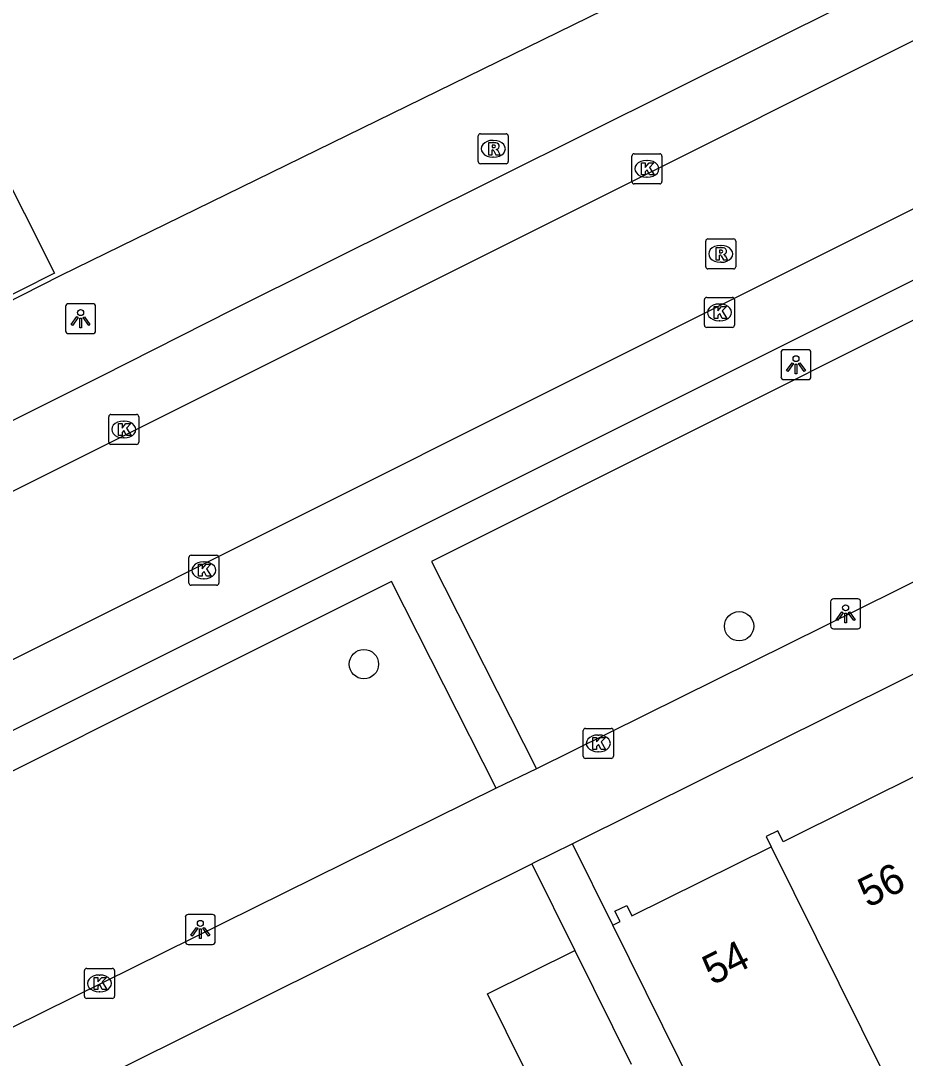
# Model space of a CAD drawing. Extents: x 157793 to 159380, y 380882 to 382313.
# Drawn here: x 158332.75 to 158362.2, y 381485.24 to 381519.79 of the extents above; entities that cross this region are included whole.
import ezdxf

# ---------------------------------------------------------------- set-up
doc = ezdxf.new("R2010")
doc.units = 0
for name, color, linetype in [('IMGEO_Boom', 7, 'Continuous'), ('IMGEO_Kolk', 7, 'Continuous'), ('IMGEO_Lichtpunt', 7, 'Continuous'), ('IMGEO_Pand', 7, 'Continuous'), ('IMGEO_Pand_nummerreeks', 7, 'Continuous'), ('IMGEO_Rijbaan_lokaal_open', 7, 'Continuous'), ('IMGEO_Rioolput', 7, 'Continuous'), ('IMGEO_Voetpad_open', 7, 'Continuous')]:
    doc.layers.add(name, color=color, linetype=linetype)

msp = doc.modelspace()

# ---------------------------------------------------------------- linework, layer by layer
at = {"layer": 'IMGEO_Boom'}
for centre in [(158356.671, 381499.625), (158344.178, 381498.362)]:
    msp.add_circle(centre, 0.489, dxfattribs=at)
at = {"layer": 'IMGEO_Kolk'}
for p, q in [((158353.175, 381515.358), (158354.027, 381515.358)), ((158353.1, 381514.432), (158353.1, 381515.284)), ((158353.588, 381515.138), (158353.613, 381515.138)), ((158354.101, 381515.284), (158354.101, 381514.432)), ((158354.027, 381514.358), (158353.175, 381514.358)), ((158353.611, 381514.578), (158353.586, 381514.578)), ((158355.517, 381509.65), (158355.517, 381510.502)), ((158355.592, 381510.576), (158356.444, 381510.576)), ((158356.518, 381510.502), (158356.518, 381509.65)), ((158356.005, 381510.356), (158356.03, 381510.356)), ((158356.028, 381509.796), (158356.003, 381509.796)), ((158356.444, 381509.576), (158355.592, 381509.576)), ((158335.757, 381506.677), (158336.609, 381506.677)), ((158335.682, 381505.751), (158335.682, 381506.603)), ((158336.17, 381506.457), (158336.195, 381506.457)), ((158336.683, 381506.603), (158336.683, 381505.751)), ((158336.609, 381505.677), (158335.757, 381505.677)), ((158336.193, 381505.897), (158336.168, 381505.897)), ((158338.349, 381501.062), (158338.349, 381501.914)), ((158338.424, 381501.988), (158339.276, 381501.988)), ((158339.35, 381501.914), (158339.35, 381501.062)), ((158338.837, 381501.768), (158338.862, 381501.768)), ((158338.86, 381501.208), (158338.835, 381501.208)), ((158339.276, 381500.988), (158338.424, 381500.988)), ((158351.483, 381495.296), (158351.483, 381496.148)), ((158351.558, 381496.222), (158352.41, 381496.222)), ((158351.971, 381496.002), (158351.996, 381496.002)), ((158352.484, 381496.148), (158352.484, 381495.296)), ((158351.994, 381495.442), (158351.969, 381495.442)), ((158352.41, 381495.222), (158351.558, 381495.222)), ((158334.874, 381487.303), (158334.874, 381488.155)), ((158334.949, 381488.229), (158335.801, 381488.229)), ((158335.875, 381488.155), (158335.875, 381487.303)), ((158335.362, 381488.009), (158335.387, 381488.009)), ((158335.385, 381487.449), (158335.36, 381487.449)), ((158335.801, 381487.229), (158334.949, 381487.229))]:
    msp.add_line(p, q, dxfattribs=at)
for points in [[(158353.175, 381515.358), (158354.027, 381515.358)], [(158353.1, 381514.432), (158353.1, 381515.284)], [(158353.421, 381515.058), (158353.544, 381515.058), (158353.544, 381514.907), (158353.674, 381515.058), (158353.838, 381515.058), (158353.692, 381514.907), (158353.845, 381514.658), (158353.693, 381514.658), (158353.608, 381514.822), (158353.544, 381514.755), (158353.544, 381514.658), (158353.421, 381514.658), (158353.421, 381515.058)], [(158354.101, 381515.284), (158354.101, 381514.432)], [(158354.027, 381514.358), (158353.175, 381514.358)], [(158355.517, 381509.65), (158355.517, 381510.502)], [(158355.592, 381510.576), (158356.444, 381510.576)], [(158356.518, 381510.502), (158356.518, 381509.65)], [(158355.838, 381510.276), (158355.961, 381510.276), (158355.961, 381510.125), (158356.091, 381510.276), (158356.255, 381510.276), (158356.109, 381510.125), (158356.262, 381509.876), (158356.11, 381509.876), (158356.025, 381510.04), (158355.961, 381509.973), (158355.961, 381509.876), (158355.838, 381509.876), (158355.838, 381510.276)], [(158356.444, 381509.576), (158355.592, 381509.576)], [(158335.757, 381506.677), (158336.609, 381506.677)], [(158335.682, 381505.751), (158335.682, 381506.603)], [(158336.003, 381506.377), (158336.126, 381506.377), (158336.126, 381506.226), (158336.256, 381506.377), (158336.42, 381506.377), (158336.274, 381506.226), (158336.427, 381505.977), (158336.275, 381505.977), (158336.19, 381506.141), (158336.126, 381506.074), (158336.126, 381505.977), (158336.003, 381505.977), (158336.003, 381506.377)], [(158336.683, 381506.603), (158336.683, 381505.751)], [(158336.609, 381505.677), (158335.757, 381505.677)], [(158338.349, 381501.062), (158338.349, 381501.914)], [(158338.424, 381501.988), (158339.276, 381501.988)], [(158339.35, 381501.914), (158339.35, 381501.062)], [(158338.67, 381501.688), (158338.793, 381501.688), (158338.793, 381501.537), (158338.923, 381501.688), (158339.087, 381501.688), (158338.941, 381501.537), (158339.094, 381501.288), (158338.942, 381501.288), (158338.857, 381501.452), (158338.793, 381501.385), (158338.793, 381501.288), (158338.67, 381501.288), (158338.67, 381501.688)], [(158339.276, 381500.988), (158338.424, 381500.988)], [(158351.483, 381495.296), (158351.483, 381496.148)], [(158351.558, 381496.222), (158352.41, 381496.222)], [(158352.484, 381496.148), (158352.484, 381495.296)], [(158351.804, 381495.922), (158351.927, 381495.922), (158351.927, 381495.771), (158352.057, 381495.922), (158352.221, 381495.922), (158352.075, 381495.771), (158352.228, 381495.522), (158352.076, 381495.522), (158351.991, 381495.686), (158351.927, 381495.619), (158351.927, 381495.522), (158351.804, 381495.522), (158351.804, 381495.922)], [(158352.41, 381495.222), (158351.558, 381495.222)], [(158334.874, 381487.303), (158334.874, 381488.155)], [(158334.949, 381488.229), (158335.801, 381488.229)], [(158335.875, 381488.155), (158335.875, 381487.303)], [(158335.195, 381487.929), (158335.318, 381487.929), (158335.318, 381487.778), (158335.448, 381487.929), (158335.612, 381487.929), (158335.466, 381487.778), (158335.619, 381487.529), (158335.467, 381487.529), (158335.382, 381487.693), (158335.318, 381487.626), (158335.318, 381487.529), (158335.195, 381487.529), (158335.195, 381487.929)], [(158335.801, 381487.229), (158334.949, 381487.229)]]:
    msp.add_lwpolyline(points, dxfattribs=at)
for centre, start, end in [((158353.177, 381515.282), 91.552, 178.448), ((158353.177, 381515.282), 91.552, 178.448), ((158354.025, 381515.282), 1.552, 88.448), ((158354.025, 381515.282), 1.552, 88.448), ((158353.177, 381514.434), 181.552, 268.448), ((158353.177, 381514.434), 181.552, 268.448), ((158354.025, 381514.434), 271.552, 358.448), ((158354.025, 381514.434), 271.552, 358.448), ((158355.594, 381510.5), 91.552, 178.448), ((158355.594, 381510.5), 91.552, 178.448), ((158356.442, 381510.5), 1.552, 88.448), ((158356.442, 381510.5), 1.552, 88.448), ((158355.594, 381509.652), 181.552, 268.448), ((158355.594, 381509.652), 181.552, 268.448), ((158356.442, 381509.652), 271.552, 358.448), ((158356.442, 381509.652), 271.552, 358.448), ((158335.759, 381506.601), 91.552, 178.448), ((158335.759, 381506.601), 91.552, 178.448), ((158336.607, 381506.601), 1.552, 88.448), ((158336.607, 381506.601), 1.552, 88.448), ((158335.759, 381505.753), 181.552, 268.448), ((158335.759, 381505.753), 181.552, 268.448), ((158336.607, 381505.753), 271.552, 358.448), ((158336.607, 381505.753), 271.552, 358.448), ((158338.426, 381501.912), 91.552, 178.448), ((158338.426, 381501.912), 91.552, 178.448), ((158339.274, 381501.912), 1.552, 88.448), ((158339.274, 381501.912), 1.552, 88.448), ((158338.426, 381501.064), 181.552, 268.448), ((158338.426, 381501.064), 181.552, 268.448), ((158339.274, 381501.064), 271.552, 358.448), ((158339.274, 381501.064), 271.552, 358.448), ((158351.56, 381496.146), 91.552, 178.448), ((158351.56, 381496.146), 91.552, 178.448), ((158352.408, 381496.146), 1.552, 88.448), ((158352.408, 381496.146), 1.552, 88.448), ((158351.56, 381495.298), 181.552, 268.448), ((158351.56, 381495.298), 181.552, 268.448), ((158352.408, 381495.298), 271.552, 358.448), ((158352.408, 381495.298), 271.552, 358.448), ((158334.951, 381488.153), 91.552, 178.448), ((158334.951, 381488.153), 91.552, 178.448), ((158335.799, 381488.153), 1.552, 88.448), ((158335.799, 381488.153), 1.552, 88.448), ((158334.951, 381487.305), 181.552, 268.448), ((158334.951, 381487.305), 181.552, 268.448), ((158335.799, 381487.305), 271.552, 358.448), ((158335.799, 381487.305), 271.552, 358.448)]:
    msp.add_arc(centre, 0.0765, start, end, dxfattribs=at)
for centre, major_axis, ratio, start_param, end_param in [((158353.587, 381514.858), (-0.387, 0.002), 0.722429, 4.712389, 7.853982), ((158353.612, 381514.858), (-0.39, 0.002), 0.717154, 1.570796, 4.712389), ((158356.004, 381510.076), (-0.387, 0.002), 0.722429, 4.712389, 7.853982), ((158356.029, 381510.076), (-0.39, 0.002), 0.717154, 1.570796, 4.712389), ((158336.169, 381506.177), (-0.387, 0.002), 0.722429, 4.712389, 7.853982), ((158336.194, 381506.177), (-0.39, 0.002), 0.717154, 1.570796, 4.712389), ((158338.836, 381501.488), (-0.387, 0.002), 0.722429, 4.712389, 7.853982), ((158338.861, 381501.488), (-0.39, 0.002), 0.717154, 1.570796, 4.712389), ((158351.97, 381495.722), (-0.387, 0.002), 0.722429, 4.712389, 7.853982), ((158351.995, 381495.722), (-0.39, 0.002), 0.717154, 1.570796, 4.712389), ((158335.361, 381487.729), (-0.387, 0.002), 0.722429, 4.712389, 7.853982), ((158335.386, 381487.729), (-0.39, 0.002), 0.717154, 1.570796, 4.712389)]:
    msp.add_ellipse(centre, major_axis=major_axis, ratio=ratio, start_param=start_param, end_param=end_param, dxfattribs=at)
at = {"layer": 'IMGEO_Lichtpunt'}
for p, q in [((158334.247, 381510.271), (158334.247, 381509.464)), ((158334.247, 381510.271), (158334.247, 381509.464)), ((158335.149, 381510.366), (158334.341, 381510.366)), ((158335.149, 381510.366), (158334.341, 381510.366)), ((158335.243, 381509.464), (158335.243, 381510.271)), ((158335.243, 381509.464), (158335.243, 381510.271)), ((158334.341, 381509.37), (158335.149, 381509.37)), ((158334.341, 381509.37), (158335.149, 381509.37)), ((158358.969, 381508.833), (158358.161, 381508.833)), ((158358.969, 381508.833), (158358.161, 381508.833)), ((158358.067, 381508.738), (158358.067, 381507.931)), ((158358.067, 381508.738), (158358.067, 381507.931)), ((158359.063, 381507.931), (158359.063, 381508.738)), ((158359.063, 381507.931), (158359.063, 381508.738)), ((158358.161, 381507.837), (158358.969, 381507.837)), ((158358.161, 381507.837), (158358.969, 381507.837)), ((158360.622, 381500.535), (158359.814, 381500.535)), ((158360.622, 381500.535), (158359.814, 381500.535)), ((158359.72, 381500.44), (158359.72, 381499.633)), ((158359.72, 381500.44), (158359.72, 381499.633)), ((158360.716, 381499.633), (158360.716, 381500.44)), ((158360.716, 381499.633), (158360.716, 381500.44)), ((158359.814, 381499.539), (158360.622, 381499.539)), ((158359.814, 381499.539), (158360.622, 381499.539)), ((158338.233, 381489.93), (158338.233, 381489.123)), ((158338.233, 381489.93), (158338.233, 381489.123)), ((158339.135, 381490.025), (158338.327, 381490.025)), ((158339.135, 381490.025), (158338.327, 381490.025)), ((158339.229, 381489.123), (158339.229, 381489.93)), ((158339.229, 381489.123), (158339.229, 381489.93)), ((158338.327, 381489.029), (158339.135, 381489.029)), ((158338.327, 381489.029), (158339.135, 381489.029))]:
    msp.add_line(p, q, dxfattribs=at)
for points in [[(158334.621, 381509.935), (158334.66, 381509.907), (158334.472, 381509.645), (158334.434, 381509.672), (158334.621, 381509.935)], [(158334.723, 381509.887), (158334.77, 381509.887), (158334.77, 381509.565), (158334.723, 381509.565), (158334.723, 381509.887)], [(158334.833, 381509.907), (158334.871, 381509.934), (158335.058, 381509.672), (158335.019, 381509.644), (158334.833, 381509.907)], [(158358.441, 381508.402), (158358.48, 381508.374), (158358.292, 381508.112), (158358.254, 381508.139), (158358.441, 381508.402)], [(158358.543, 381508.354), (158358.59, 381508.354), (158358.59, 381508.032), (158358.543, 381508.032), (158358.543, 381508.354)], [(158358.653, 381508.374), (158358.691, 381508.401), (158358.878, 381508.139), (158358.839, 381508.111), (158358.653, 381508.374)], [(158360.094, 381500.104), (158360.133, 381500.076), (158359.945, 381499.814), (158359.907, 381499.841), (158360.094, 381500.104)], [(158360.196, 381500.056), (158360.243, 381500.056), (158360.243, 381499.734), (158360.196, 381499.734), (158360.196, 381500.056)], [(158360.306, 381500.076), (158360.344, 381500.103), (158360.531, 381499.841), (158360.492, 381499.813), (158360.306, 381500.076)], [(158338.607, 381489.594), (158338.646, 381489.566), (158338.458, 381489.304), (158338.42, 381489.331), (158338.607, 381489.594)], [(158338.709, 381489.546), (158338.756, 381489.546), (158338.756, 381489.224), (158338.709, 381489.224), (158338.709, 381489.546)], [(158338.819, 381489.566), (158338.857, 381489.593), (158339.044, 381489.331), (158339.005, 381489.303), (158338.819, 381489.566)]]:
    msp.add_lwpolyline(points, dxfattribs=at)
for centre in [(158334.746, 381510.069), (158358.566, 381508.536), (158360.219, 381500.238), (158338.732, 381489.728)]:
    msp.add_circle(centre, 0.0994, dxfattribs=at)
for centre, start, end in [((158334.341, 381510.271), 90, 180), ((158334.341, 381510.271), 90, 180), ((158335.149, 381510.271), 0, 90), ((158335.149, 381510.271), 0, 90), ((158334.341, 381509.464), 180, 270), ((158334.341, 381509.464), 180, 270), ((158335.149, 381509.464), 270, 0), ((158335.149, 381509.464), 270, 360), ((158358.161, 381508.738), 90, 180), ((158358.161, 381508.738), 90, 180), ((158358.969, 381508.738), 0, 90), ((158358.969, 381508.738), 0, 90), ((158358.161, 381507.931), 180, 270), ((158358.161, 381507.931), 180, 270), ((158358.969, 381507.931), 270, 0), ((158358.969, 381507.931), 270, 360), ((158359.814, 381500.44), 90, 180), ((158359.814, 381500.44), 90, 180), ((158360.622, 381500.44), 0, 90), ((158360.622, 381500.44), 0, 90), ((158359.814, 381499.633), 180, 270), ((158359.814, 381499.633), 180, 270), ((158360.622, 381499.633), 270, 0), ((158360.622, 381499.633), 270, 360), ((158338.327, 381489.93), 90, 180), ((158338.327, 381489.93), 90, 180), ((158339.135, 381489.93), 0, 90), ((158339.135, 381489.93), 0, 90), ((158338.327, 381489.123), 180, 270), ((158338.327, 381489.123), 180, 270), ((158339.135, 381489.123), 270, 0), ((158339.135, 381489.123), 270, 360)]:
    msp.add_arc(centre, 0.0946, start, end, dxfattribs=at)
at = {"layer": 'IMGEO_Pand'}
for points in [[(158329.562, 381514.225), (158331.856, 381515.384), (158333.874, 381511.388), (158331.58, 381510.229), (158329.562, 381514.225)], [(158362.913, 381494.818), (158358.143, 381492.448), (158357.962, 381492.811), (158357.573, 381492.618), (158357.737, 381492.281)], [(158352.463, 381489.666), (158352.708, 381489.787), (158352.537, 381490.13), (158352.93, 381490.325), (158353.102, 381489.979), (158357.737, 381492.281)], [(158357.737, 381492.281), (158362.245, 381483.192)], [(158356.951, 381480.633), (158354.687, 381485.189), (158352.463, 381489.666)], [(158350.168, 381483.597), (158348.29, 381487.377), (158351.202, 381488.824)], [(158351.202, 381488.824), (158353.08, 381485.044)]]:
    msp.add_lwpolyline(points, dxfattribs=at)
at = {"layer": 'IMGEO_Rijbaan_lokaal_open'}
for points in [[(158364.219, 381519.993), (158323.239, 381499.498)], [(158325.561, 381495.049), (158366.656, 381515.626)]]:
    msp.add_lwpolyline(points, dxfattribs=at)
at = {"layer": 'IMGEO_Rioolput'}
for p, q in [((158348.061, 381516.026), (158348.913, 381516.026)), ((158347.986, 381515.1), (158347.986, 381515.952)), ((158348.474, 381515.806), (158348.499, 381515.806)), ((158348.987, 381515.952), (158348.987, 381515.1)), ((158348.913, 381515.026), (158348.061, 381515.026)), ((158348.497, 381515.246), (158348.472, 381515.246)), ((158355.56, 381511.599), (158355.56, 381512.451)), ((158355.635, 381512.525), (158356.487, 381512.525)), ((158356.048, 381512.305), (158356.073, 381512.305)), ((158356.561, 381512.451), (158356.561, 381511.599)), ((158356.487, 381511.525), (158355.635, 381511.525)), ((158356.071, 381511.745), (158356.046, 381511.745))]:
    msp.add_line(p, q, dxfattribs=at)
for points in [[(158348.061, 381516.026), (158348.913, 381516.026)], [(158347.986, 381515.1), (158347.986, 381515.952)], [(158348.575, 381515.724), (158348.323, 381515.726), (158348.323, 381515.326)], [(158348.987, 381515.952), (158348.987, 381515.1)], [(158348.323, 381515.326), (158348.447, 381515.326), (158348.447, 381515.488), (158348.458, 381515.488)], [(158348.501, 381515.645), (158348.447, 381515.645), (158348.447, 381515.564)], [(158348.447, 381515.564), (158348.499, 381515.564)], [(158348.505, 381515.459), (158348.576, 381515.326), (158348.716, 381515.326), (158348.651, 381515.452)], [(158348.913, 381515.026), (158348.061, 381515.026)], [(158355.56, 381511.599), (158355.56, 381512.451)], [(158355.635, 381512.525), (158356.487, 381512.525)], [(158356.149, 381512.223), (158355.897, 381512.225), (158355.897, 381511.825)], [(158356.561, 381512.451), (158356.561, 381511.599)], [(158355.897, 381511.825), (158356.021, 381511.825), (158356.021, 381511.987), (158356.032, 381511.987)], [(158356.075, 381512.144), (158356.021, 381512.144), (158356.021, 381512.063)], [(158356.021, 381512.063), (158356.073, 381512.063)], [(158356.079, 381511.958), (158356.15, 381511.825), (158356.29, 381511.825), (158356.225, 381511.951)], [(158356.487, 381511.525), (158355.635, 381511.525)]]:
    msp.add_lwpolyline(points, dxfattribs=at)
for centre, radius, start, end in [((158348.063, 381515.95), 0.0765, 91.552, 178.448), ((158348.063, 381515.95), 0.0765, 91.552, 178.448), ((158348.911, 381515.95), 0.0765, 1.552, 88.448), ((158348.911, 381515.95), 0.0765, 1.552, 88.448), ((158348.574, 381515.614), 0.109, 350.3612, 89.416), ((158348.457, 381515.435), 0.0533, 26.0293, 88.6989), ((158348.483, 381515.753), 0.19, 274.7715, 282.9687), ((158348.507, 381515.549), 0.0964, 77.0061, 93.1865), ((158348.521, 381515.606), 0.0378, 276.6634, 79.6772), ((158348.572, 381515.614), 0.112, 277.5842, 350.9817), ((158348.556, 381515.399), 0.108, 29.5134, 73.7905), ((158348.063, 381515.102), 0.0765, 181.552, 268.448), ((158348.063, 381515.102), 0.0765, 181.552, 268.448), ((158348.911, 381515.102), 0.0765, 271.552, 358.448), ((158348.911, 381515.102), 0.0765, 271.552, 358.448), ((158355.637, 381512.449), 0.0765, 91.552, 178.448), ((158355.637, 381512.449), 0.0765, 91.552, 178.448), ((158356.148, 381512.113), 0.109, 350.3612, 89.416), ((158356.485, 381512.449), 0.0765, 1.552, 88.448), ((158356.485, 381512.449), 0.0765, 1.552, 88.448), ((158356.031, 381511.934), 0.0533, 26.0293, 88.6989), ((158356.057, 381512.252), 0.19, 274.7715, 282.9687), ((158356.081, 381512.048), 0.0964, 77.0061, 93.1865), ((158356.095, 381512.105), 0.0378, 276.6634, 79.6772), ((158356.146, 381512.113), 0.112, 277.5842, 350.9817), ((158356.13, 381511.898), 0.108, 29.5134, 73.7905), ((158355.637, 381511.601), 0.0765, 181.552, 268.448), ((158355.637, 381511.601), 0.0765, 181.552, 268.448), ((158356.485, 381511.601), 0.0765, 271.552, 358.448), ((158356.485, 381511.601), 0.0765, 271.552, 358.448)]:
    msp.add_arc(centre, radius, start, end, dxfattribs=at)
for centre, major_axis, ratio, start_param, end_param in [((158348.473, 381515.526), (-0.387, 0.002), 0.722429, 4.712389, 7.853982), ((158348.498, 381515.526), (-0.39, 0.002), 0.717154, 1.570796, 4.712389), ((158356.047, 381512.025), (-0.387, 0.002), 0.722429, 4.712389, 7.853982), ((158356.072, 381512.025), (-0.39, 0.002), 0.717154, 1.570796, 4.712389)]:
    msp.add_ellipse(centre, major_axis=major_axis, ratio=ratio, start_param=start_param, end_param=end_param, dxfattribs=at)
at = {"layer": 'IMGEO_Voetpad_open'}
for points in [[(158314.661, 381501.53), (158325.988, 381507.244), (158331.554, 381510.024), (158334.071, 381511.302), (158354.167, 381521.141), (158359.971, 381524.023), (158359.996, 381524.036)], [(158290.721, 381485.284), (158292.396, 381486.391), (158323.691, 381502.101), (158328.215, 381504.357), (158335.434, 381507.954), (158339.842, 381510.182), (158360.378, 381520.424)], [(158402.954, 381518.145), (158366.45, 381500), (158351.122, 381492.381)], [(158375.088, 381507.338), (158371.522, 381514.342), (158346.435, 381501.779), (158349.93, 381494.878)], [(158364.631, 381512.222), (158329.72, 381494.777)], [(158375.088, 381507.338), (158349.93, 381494.878)], [(158348.584, 381494.228), (158345.094, 381501.119), (158324.627, 381490.884)], [(158349.93, 381494.878), (158348.584, 381494.228)], [(158348.584, 381494.228), (158326.422, 381483.272), (158325.707, 381482.947)], [(158351.122, 381492.381), (158349.769, 381491.708)], [(158352.463, 381489.666), (158351.122, 381492.381)], [(158327.204, 381480.491), (158349.769, 381491.708)], [(158349.769, 381491.708), (158351.202, 381488.824)]]:
    msp.add_lwpolyline(points, dxfattribs=at)

# ---------------------------------------------------------------- texts
at = {"layer": 'IMGEO_Pand_nummerreeks'}
for s, rotation, p in [('56', 26.4821, (158360.959, 381490.233)), ('54', 26.4796, (158355.777, 381487.652))]:
    msp.add_text(s, height=1, rotation=rotation, dxfattribs=at).set_placement(p)

doc.saveas('drawing.dxf')
